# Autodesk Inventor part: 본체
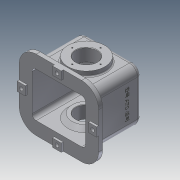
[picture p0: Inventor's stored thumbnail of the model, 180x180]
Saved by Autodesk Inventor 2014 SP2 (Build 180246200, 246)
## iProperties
Created: 2014-11
Part Number: 본체
Material: 알루미늄 6061
Document SubType Name: Modeling
Designer: 201-12
Density: 2.71 g/cm^3
Appearance: 알루미늄 - 평지
Mass: 2962.33 g
Surface Area: 2124.66 cm^2
Volume: 1093.11 cm^3
Author: 201-12
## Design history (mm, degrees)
sketch "스케치2"
  geometry: L1 (-98, 87)-(98, 87); L2 (98, 87)-(98, -87); L3 (98, -87)-(-98, -87); L4 (-98, -87)-(-98, 87); L5 (-98, 87)-(98, -87); L6 (98, 87)-(-98, -87); 1 further point
  constraints: 12 end point, 2 midpoint, 2 parallel, 1 horizontal, 1 perpendicular
  dimensions: "d2" = 196 distance of L2.end L3.end; "d3" = 174 distance of L1.end L2.end
extrude "돌출1" new body sketch "스케치2" distance "d4" = 10; taper "d5" = 0 deg
sketch "스케치3"
  geometry: L1 (-76, 65)-(76, 65); L2 (76, 65)-(76, -65); L3 (76, -65)-(-76, -65); L4 (-76, -65)-(-76, 65); L5 (-76, 65)-(76, -65); L6 (76, 65)-(-76, -65); 1 further point
  constraints: 12 end point, 2 midpoint, 2 parallel, 1 horizontal, 1 perpendicular
  dimensions: "d6" = 152 distance of L2.end L3.end; "d7" = 130 distance of L1.end L2.end
extrude "돌출2" join sketch "스케치3" distance "d8" = 118; taper "d9" = 0 deg
node "작업 평면2"
node "작업 평면3"
sketch "스케치5"
  geometry: L1 (76, -65)-(76, 65) reference; 1 further point
node "작업 평면5"
  node "작업 평면4"
sketch "스케치15"
  geometry: L1 (-98, -10)-(98, -10) reference; L2 (0, 58)-(17.88, 142.121); L3 (0, 58)-(54.453, 58); L4 (17.88, 142.121)-(-12.442, 148.566); L5 (-12.442, 148.566)-(-19.259, 116.497); L6 (-19.259, 116.497)-(11.064, 110.052); L7 (11.064, 110.052)-(17.88, 142.121); 1 further point
  constraints: 12 end point, 2 parallel, 2 perpendicular, 1 collinear, 1 vertical alignment
  dimensions: "d95" = 68 distance from line of L1 L2.start; "d96" = 78 deg angle of L3 L2; "d97" = 86 distance of L2.start L2.end; "d98" = 31 distance of L2.end L4.end; "d99" = 32.78514 distance of L4.end L5.end
revolve "회전2" sketch "스케치15" stored, may be unused: angle "d100" = 90 deg
sketch "스케치4"
  geometry: L1 (-66, 55)-(66, 55); L2 (66, 55)-(66, -55); L3 (66, -55)-(-66, -55); L4 (-66, -55)-(-66, 55); L5 (-66, 55)-(66, -55); L6 (66, 55)-(-66, -55); 1 further point
  constraints: 12 end point, 2 midpoint, 2 parallel, 1 horizontal, 1 perpendicular
  dimensions: "d10" = 132 distance of L2.end L3.end; "d11" = 110 distance of L1.end L2.end
extrude "돌출3" cut sketch "스케치4" distance "d12" = 118; taper "d13" = 0 deg
sketch "스케치7"
  geometry: L1 (174, -10)-(-22, -10) reference; L2 (174, 0)-(-22, 0) reference; C1 r 45.5 at (76, 58); 2 further points
  constraints: 1 centre point, 1 midpoint, 1 vertical alignment
  dimensions: "d22" = 91 diameter of C1; "d23" = 68 distance from line of C1.centre L1
extrude "돌출5" join sketch "스케치7" distance "d24" = 12; taper "d25" = 0 deg
sketch "스케치8"
  geometry: C1 r 45.5 at (0, 0) reference; C2 r 26 at (0, 0); 1 further point
  constraints: 1 centre point, 1 coincident
  dimensions: "d26" = 52 diameter of C2
extrude "돌출6" cut sketch "스케치8" stored distance "d27" = 12; taper "d28" = 0 deg
sketch "스케치9"
  geometry: L1 (58, 0)-(58, -74.77); L2 (84, -77)-(84, -55) reference; L3 (32, -77)-(32, -55) reference; L4 (84, -55)-(84, -45); L5 (84, -45)-(93.5, -45); L6 (93.5, -45)-(103.5, -55); L7 (103.5, -55)-(84, -55); 1 further point
  constraints: 10 end point, 3 parallel, 1 horizontal alignment, 1 perpendicular, 1 vertical
  dimensions: "d29" = 26 horizontal distance of L2.start L1.end; "d30" = 74.76996 distance of L1.start L1.end; "d31" = 71 diameter of L5.end L1; "d32" = 91 diameter of L6.end L1; "d33" = 10 distance of L2.end L4.end
revolve "회전1" sketch "스케치9" stored, may be unused: angle "d34" = 90 deg
sketch "스케치11" dims "d35" = 70
  geometry: C1 r 26 at (0, 0) reference; C2 r 45.5 at (0, 0) reference; 6 further points
  constraints: 3 vertical alignment, 1 coincident, 7 other
  dimensions: "d38" = 360 deg dimension on point (0, 0) point (0, 35) (derived)
hole "구멍1" sketch "스케치11" at (0, 35), (-35, 0), (0, -35), (35, 0) diameter "d40" = 3.242; stored, may be unused: countersink angle "d44" = 90 deg, drill point angle "d46" = 118 deg; dims "d41" = 13, "d42" = 4, "d43" = 2, "d45" = 16
sketch "스케치12"
  geometry: L1 (98, 87)-(-98, 87) reference; L2 (-98, 87)-(-98, -87) reference; L3 (-98, -87)-(98, -87) reference; L4 (98, -87)-(98, 87) reference; L5 (-11, 87)-(11, 87); L6 (11, 87)-(11, 67); L7 (11, 67)-(-11, 67); L8 (-11, 67)-(-11, 87); L9 (-98, 11)-(-78, 11); L10 (-78, 11)-(-78, -11); L11 (-78, -11)-(-98, -11); L12 (-98, -11)-(-98, 11); L13 (-11, -67)-(11, -67); L14 (11, -67)-(11, -87); L15 (11, -87)-(-11, -87); L16 (-11, -87)-(-11, -67); L17 (78, 11)-(98, 11); L18 (98, 11)-(98, -11); L19 (98, -11)-(78, -11); L20 (78, -11)-(78, 11); 1 further point
  constraints: 32 end point, 8 parallel, 4 horizontal, 4 perpendicular, 4 point on line
  dimensions: "d47" = 22 distance of L5.start L5.end; "d48" = 20 distance of L5.end L6.end; "d49" = 11 distance from line of L6 point (0, 0); "d50" = 22 distance of L17.end L18.end; "d51" = 22 distance between parallel lines of L16 L14; "d52" = 22 distance between parallel lines of L11 L9; "d53" = 11 distance from line of point (0, 0) L11; "d54" = 20 distance of L10.end L11.end; "d55" = 20 distance of L15.end L13.start; "d56" = 20 distance of L18.end L19.end; "d57" = 11 distance from line of point (0, 0) L19; "d58" = 11 distance from line of point (0, 0) L16
extrude "돌출7" join sketch "스케치12" distance "d59" = 5; taper "d60" = 0 deg
sketch "스케치13"
  geometry: L1 (98, -87)-(-98, -87) reference; L2 (98, 87)-(98, -87) reference; L3 (-98, 87)-(98, 87) reference; L4 (-98, -87)-(-98, 87) reference; 5 further points
  constraints: 2 horizontal alignment, 2 vertical alignment
  dimensions: "d61" = 10 distance from line of L3 point (0, 77); "d62" = 10 distance from line of L2 point (88, 0); "d63" = 10 distance from line of L1 point (0, -77); "d64" = 10 distance from line of L4 point (-88, 0)
hole "구멍2" sketch "스케치13" at (88, 0), (0, 77), (-88, 0), (0, -77) diameter "d65" = 9; stored, may be unused: countersink angle "d69" = 90 deg, drill point angle "d71" = 118 deg; dims "d66" = 13, "d67" = 14, "d68" = 8.6, "d70" = 16
fillet "모깎기1" dims "d72" = 42
fillet "모깎기2" dims "d73" = 20
fillet "모깎기4" dims "d75" = 10
fillet "모깎기5" dims "d76" = 3
hole "구멍3" diameter "d79" = 30; stored, may be unused: countersink angle "d83" = 90 deg, drill point angle "d85" = 118 deg; dims "d80" = 13, "d81" = 42, "d82" = 25, "d84" = 16, "d101" = 10, "d102" = 10
fillet "모깎기6" dims "d86" = 0.3
node "작업 평면7"
sketch "스케치14"
  geometry: L1 (34, -118)-(0, -118) reference; 2 further points
  constraints: 1 vertical alignment, 1 other
  dimensions: "d88" = 92 distance from line of L1 point (45, -26)
feature "엠보싱1" sketch "스케치14" dims "d2" = 196, "d3" = 174, "d10" = 132, "d11" = 110, "d89" = 1, "d90" = 0
chamfer "모따기1" distance "d91" = 1; stored, may be unused: second distance "d92" = 2, angle "d93" = 45 deg
node "솔리드1"
mirror "대칭2"
other parameters: "d15" = -68, "d16" = 12 deg, "d17" = -12 deg, "d18" = -86, "d87" = 72
